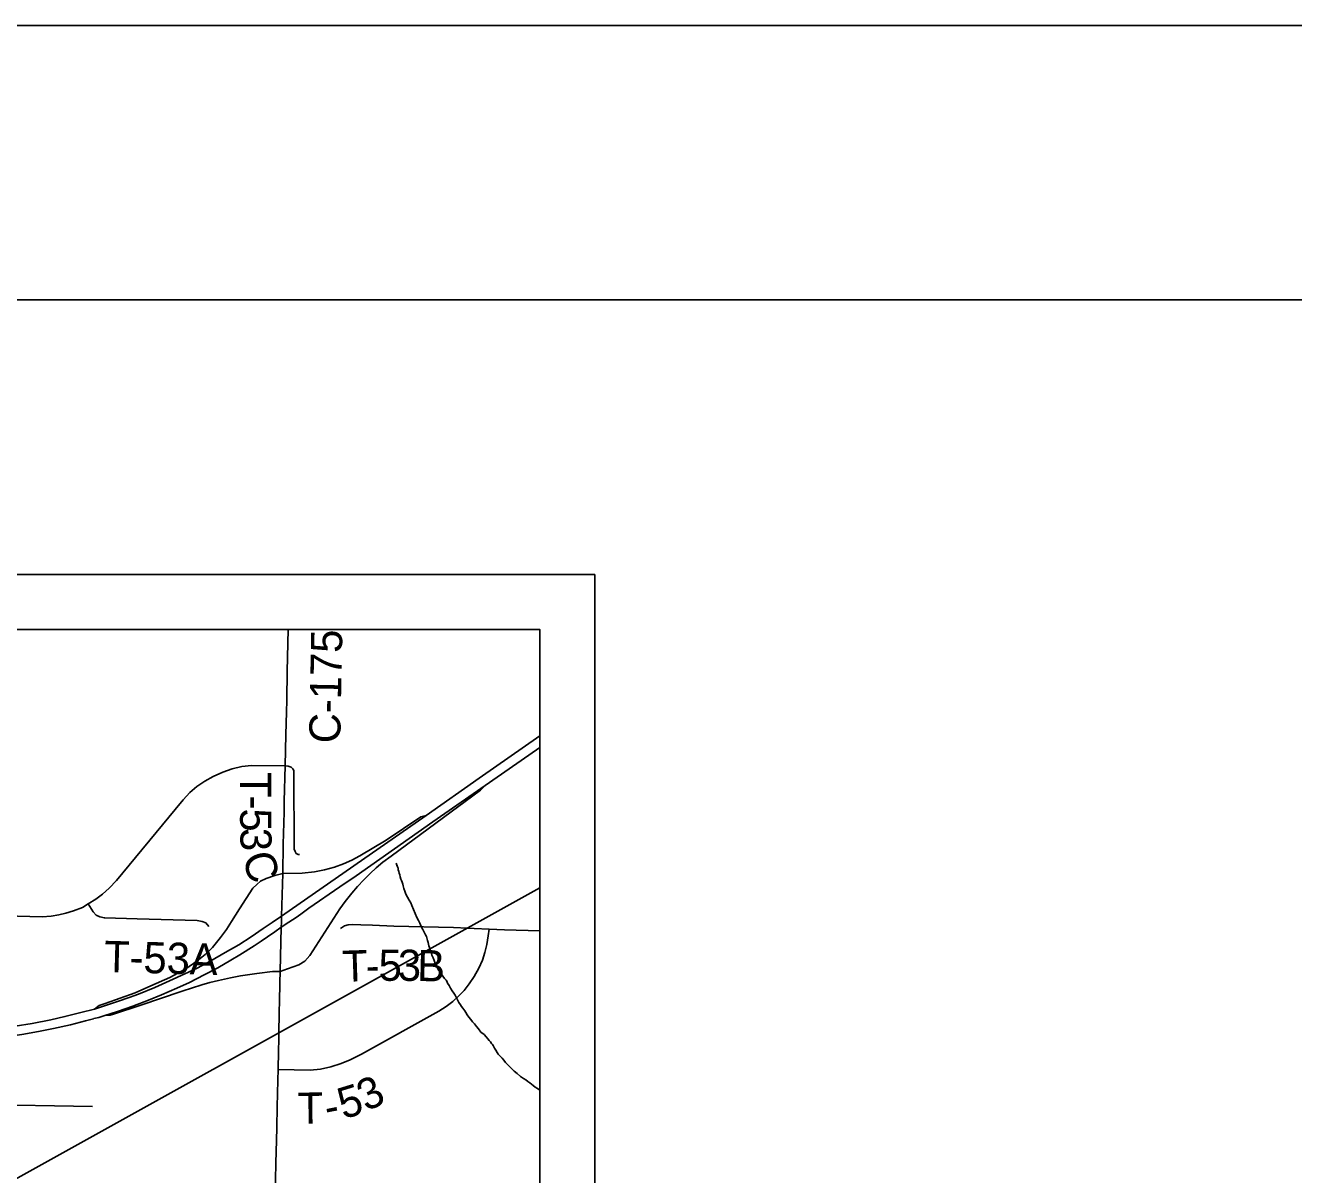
# Model space of a CAD drawing. Extents: x 0 to 34, y 0 to 22.
# Drawn here: x 29.379 to 31.69, y 19.908 to 22 of the extents above; entities that cross this region are included whole.
import ezdxf

# ---------------------------------------------------------------- set-up
doc = ezdxf.new("R2010")
doc.units = 0
for name, color, linetype in [('GM_X_City_Street', 7, 'Continuous'), ('GM_X_County_Road', 7, 'Continuous'), ('GM_X_County_Road_Text', 7, 'Continuous'), ('GM_X_Interchange_Ramps', 7, 'Continuous'), ('GM_X_Minor_River', 7, 'Continuous'), ('GM_X_Rail_Line', 7, 'Continuous'), ('GM_X_State_Route', 7, 'Continuous'), ('GM_X_Township_Road', 7, 'Continuous'), ('GM_X_Township_Road_Text', 7, 'Continuous'), ('GM_X_US_Route', 7, 'Continuous'), ('SH_Border', 7, 'Continuous'), ('SH_Cut_Line', 7, 'Continuous'), ('SH_Data', 7, 'Continuous')]:
    doc.layers.add(name, color=color, linetype=linetype)

msp = doc.modelspace()

# ---------------------------------------------------------------- linework, layer by layer
at = {"layer": 'GM_X_City_Street'}
msp.add_lwpolyline([(29.0843, 20.0386), (29.502, 20.0316)], dxfattribs=at)
at = {"layer": 'GM_X_County_Road'}
for points in [[(29.8555, 20.7716), (29.8566, 20.8244), (29.8584, 20.9)], [(29.8526, 20.6517), (29.8539, 20.7087), (29.855, 20.7498), (29.8555, 20.7716)], [(29.6523, 20.5721), (29.6669, 20.5897), (29.6793, 20.6033), (29.6918, 20.6142), (29.7062, 20.6241), (29.7214, 20.6326), (29.7394, 20.6405), (29.7562, 20.6461), (29.7736, 20.6504), (29.7911, 20.6523), (29.8526, 20.6517)], [(29.8506, 20.5677), (29.8511, 20.5875), (29.8526, 20.6517)], [(29.3428, 20.3785), (29.41, 20.3768), (29.4264, 20.3781), (29.4402, 20.3804), (29.4531, 20.3834), (29.4669, 20.3876), (29.4833, 20.3942), (29.4938, 20.4005), (29.5076, 20.409), (29.5198, 20.4179), (29.5323, 20.4291), (29.5454, 20.4432), (29.6523, 20.5721)], [(29.8483, 20.4557), (29.8492, 20.5092), (29.8506, 20.5677)]]:
    msp.add_lwpolyline(points, dxfattribs=at)
at = {"layer": 'GM_X_Interchange_Ramps'}
for points in [[(29.8433, 20.2774), (29.8568, 20.2821), (29.8775, 20.2893), (29.8887, 20.2959), (29.8979, 20.3068), (29.9522, 20.3913), (29.962, 20.4047), (29.9742, 20.4199), (29.9847, 20.4324), (29.9959, 20.4445), (30.0074, 20.456), (30.0186, 20.4662), (30.0308, 20.4764), (30.0456, 20.4876), (30.2088, 20.6077), (30.2172, 20.6163)], [(30.1096, 20.5615), (30.0999, 20.5587), (30.0369, 20.5162), (29.9887, 20.4879), (29.9742, 20.48), (29.9588, 20.4735), (29.9423, 20.4675), (29.9242, 20.4626), (29.9062, 20.459), (29.8835, 20.4564), (29.8483, 20.4557)]]:
    msp.add_lwpolyline(points, dxfattribs=at)
at = {"layer": 'GM_X_Minor_River'}
for points in [[(30.0547, 20.4746), (30.0572, 20.4681), (30.0561, 20.4708), (30.0572, 20.4681), (30.0583, 20.4658), (30.0586, 20.4627), (30.0596, 20.4596), (30.0603, 20.4566), (30.0613, 20.4531), (30.0623, 20.4497), (30.0634, 20.4455), (30.0648, 20.4428), (30.0659, 20.4401), (30.0669, 20.4366), (30.0679, 20.4332), (30.0689, 20.4286), (30.0707, 20.4236), (30.0728, 20.4182), (30.0757, 20.4128), (30.0786, 20.4074), (30.0815, 20.4024), (30.0836, 20.3978), (30.0864, 20.3904), (30.0893, 20.3828), (30.0925, 20.3758), (30.0957, 20.3704), (30.0982, 20.3654), (30.1007, 20.3596), (30.1036, 20.3538), (30.1061, 20.3488), (30.1083, 20.3442), (30.1101, 20.3411), (30.1108, 20.3384), (30.1118, 20.3338), (30.1132, 20.3304), (30.1138, 20.3273), (30.1145, 20.3243), (30.1156, 20.3208), (30.117, 20.317), (30.1184, 20.3127), (30.1201, 20.3074), (30.1222, 20.3024), (30.1244, 20.2974), (30.1261, 20.2928), (30.1279, 20.2893), (30.1294, 20.2866), (30.1304, 20.2843), (30.1311, 20.2823), (30.1329, 20.2789), (30.1362, 20.2742), (30.1399, 20.2688), (30.1432, 20.2645), (30.1457, 20.2618), (30.1472, 20.2598), (30.1486, 20.2564), (30.1512, 20.2521), (30.154, 20.2471), (30.1569, 20.2421), (30.1598, 20.2378), (30.1624, 20.2343), (30.1638, 20.2316), (30.1657, 20.2285), (30.1674, 20.2247), (30.1692, 20.2208), (30.1718, 20.2169), (30.174, 20.2138), (30.1762, 20.2107), (30.178, 20.2084), (30.1798, 20.2057), (30.182, 20.2026), (30.1845, 20.1983), (30.1874, 20.1941), (30.1907, 20.1902), (30.194, 20.1859), (30.1977, 20.182), (30.2014, 20.1773), (30.2051, 20.173), (30.2094, 20.1672), (30.2154, 20.1625), (30.2191, 20.1586), (30.222, 20.155), (30.2246, 20.1516), (30.2268, 20.1492), (30.2286, 20.1465), (30.2301, 20.1446), (30.2315, 20.1426), (30.2326, 20.1403), (30.234, 20.1376), (30.2362, 20.1341), (30.2391, 20.1302), (30.2409, 20.1271), (30.2431, 20.1244), (30.2453, 20.1221), (30.2479, 20.1193), (30.2509, 20.1158), (30.2542, 20.1119), (30.27, 20.0959), (30.2756, 20.0915), (30.2811, 20.0861), (30.2871, 20.0828), (30.2912, 20.0801)], [(30.2912, 20.0801), (30.2949, 20.0773), (30.2983, 20.0745), (30.3012, 20.0722), (30.3046, 20.0698), (30.3083, 20.067), (30.3124, 20.0642), (30.3167, 20.0615)]]:
    msp.add_lwpolyline(points, dxfattribs=at)
at = {"layer": 'GM_X_Rail_Line'}
msp.add_lwpolyline([(29.1835, 19.8007), (29.9023, 20.1997), (30.3167, 20.43)], dxfattribs=at)
at = {"layer": 'GM_X_State_Route'}
for p, q in [((29.755, 20.3685), (29.7696, 20.3912)), ((29.8433, 20.2774), (29.843, 20.2574))]:
    msp.add_line(p, q, dxfattribs=at)
for points in [[(29.7696, 20.3912), (29.794, 20.4291), (29.8009, 20.436), (29.8075, 20.4416), (29.8184, 20.4468), (29.8341, 20.4521), (29.8483, 20.4557), (29.846, 20.3781), (29.8458, 20.3665), (29.8456, 20.358), (29.8433, 20.2774)], [(29.5051, 20.2091), (29.5139, 20.2153), (29.5251, 20.219), (29.5793, 20.2387), (29.6079, 20.2512), (29.6428, 20.2666), (29.672, 20.2824), (29.6921, 20.2959), (29.7069, 20.3081), (29.7204, 20.3212), (29.7348, 20.3393), (29.7457, 20.3541), (29.755, 20.3685)], [(29.6672, 20.2424), (29.6819, 20.2473), (29.7008, 20.2532), (29.7156, 20.2576), (29.7315, 20.2611), (29.7532, 20.266), (29.7716, 20.2697), (29.8011, 20.2735), (29.8295, 20.2771), (29.8433, 20.2774)], [(29.5895, 20.2161), (29.6633, 20.2411), (29.6672, 20.2424)], [(29.843, 20.2574), (29.8428, 20.2464), (29.8423, 20.2323)], [(29.5243, 20.1974), (29.5338, 20.1981), (29.5403, 20.1995), (29.5895, 20.2161)], [(29.8423, 20.2323), (29.8422, 20.2282), (29.8417, 20.199), (29.8413, 20.1682), (29.8411, 20.1539)], [(29.8411, 20.1539), (29.8407, 20.1325), (29.84, 20.0988), (29.8396, 20.0796), (29.8384, 20.031), (29.8378, 19.9931), (29.8371, 19.9695), (29.8359, 19.929), (29.8346, 19.8657)]]:
    msp.add_lwpolyline(points, dxfattribs=at)
at = {"layer": 'GM_X_Township_Road'}
for points in [[(28.8021, 16.3696), (29.7483, 16.3505), (30.2361, 16.3375), (30.2681, 16.3359), (30.2735, 16.3357), (30.315, 16.335), (30.3167, 16.335), (30.3167, 20.9), (28.9104, 20.9)], [(29.8526, 20.6517), (29.8583, 20.651), (29.8635, 20.6496), (29.8666, 20.6465), (29.8687, 20.6434), (29.8687, 20.6399), (29.8694, 20.5001), (29.8708, 20.4956), (29.8725, 20.4921), (29.8764, 20.4904), (29.8791, 20.4904)], [(29.4938, 20.4005), (29.503, 20.386), (29.5086, 20.3801), (29.5152, 20.3768), (29.5234, 20.3748), (29.5244, 20.3748)], [(29.5244, 20.3748), (29.583, 20.3735), (29.6924, 20.3702)], [(29.6924, 20.3702), (29.7013, 20.3686), (29.7079, 20.3659), (29.7135, 20.3594)], [(29.84, 20.0988), (29.8982, 20.0976), (29.917, 20.0997), (29.936, 20.1035), (29.9548, 20.1097), (29.9714, 20.1167), (29.9919, 20.1271), (30.1324, 20.2052), (30.146, 20.2135), (30.1581, 20.2229), (30.1692, 20.2333), (30.1786, 20.2426), (30.1879, 20.2548), (30.197, 20.2683), (30.2056, 20.2832), (30.2122, 20.2978), (30.2167, 20.3117), (30.2202, 20.3266), (30.2226, 20.3426), (30.2244, 20.3544)], [(29.9538, 20.3558), (29.9607, 20.3604), (29.9673, 20.3623), (29.9752, 20.3627), (29.9905, 20.3622), (30.0116, 20.3615), (30.0508, 20.3602), (30.1595, 20.3572), (30.1857, 20.356)], [(30.1857, 20.356), (30.1968, 20.3555), (30.2244, 20.3544)], [(30.2244, 20.3544), (30.252, 20.3533), (30.3167, 20.3512)]]:
    msp.add_lwpolyline(points, dxfattribs=at)
at = {"layer": 'GM_X_US_Route'}
for p, q in [((30.2064, 20.6293), (30.3167, 20.7065)), ((30.1096, 20.5615), (30.2064, 20.6293))]:
    msp.add_line(p, q, dxfattribs=at)
for points in [[(30.2172, 20.6163), (30.2964, 20.6713), (30.3167, 20.6855)], [(29.8456, 20.358), (29.8596, 20.3675), (29.8727, 20.3759), (29.8812, 20.382), (29.8957, 20.3926), (29.9521, 20.4313), (29.9818, 20.4518), (30.1217, 20.5501), (30.2172, 20.6163)], [(29.8292, 20.3668), (29.846, 20.3781), (30.1096, 20.5615)], [(29.361, 20.1779), (29.3916, 20.1825), (29.4258, 20.1894), (29.4514, 20.1953), (29.4803, 20.2025), (29.5051, 20.2091), (29.5293, 20.2167), (29.5491, 20.2232), (29.5688, 20.2301), (29.5856, 20.2364), (29.6152, 20.2482), (29.6421, 20.2601), (29.6701, 20.2729), (29.6924, 20.2837), (29.7174, 20.2969), (29.7437, 20.312), (29.7681, 20.3262), (29.7907, 20.3406), (29.8124, 20.3554), (29.8292, 20.3668)], [(29.5243, 20.1974), (29.5474, 20.2047), (29.575, 20.2143), (29.6035, 20.2251), (29.6277, 20.2349), (29.6551, 20.2468), (29.6782, 20.2576), (29.7054, 20.2712), (29.7301, 20.2843), (29.7539, 20.2978), (29.7699, 20.3075), (29.7961, 20.3242), (29.8087, 20.3327), (29.8204, 20.3405), (29.8337, 20.3497), (29.8456, 20.358)], [(29.5044, 20.1915), (29.5131, 20.1939), (29.5243, 20.1974)], [(29.0865, 20.149), (29.0875, 20.149), (29.1993, 20.1493), (29.2371, 20.1501), (29.2676, 20.1514), (29.2948, 20.1532), (29.3208, 20.1557), (29.3473, 20.1589), (29.3731, 20.1627), (29.4031, 20.1679), (29.4305, 20.1734), (29.4614, 20.1804), (29.4891, 20.1874), (29.5035, 20.1912), (29.5044, 20.1915)]]:
    msp.add_lwpolyline(points, dxfattribs=at)
at = {"layer": 'SH_Border'}
msp.add_lwpolyline([(1.5, 21.5), (33.5, 21.5), (33.5, 0.5), (1.5, 0.5)], close=True, dxfattribs=at)
at = {"layer": 'SH_Cut_Line'}
msp.add_lwpolyline([(0, 0), (34, 0), (34, 22), (0, 22)], close=True, dxfattribs=at)
at = {"layer": 'SH_Data'}
for points in [[(23.4167, 21), (30.4167, 21), (30.4167, 14), (23.4167, 14)], [(23.5167, 20.9), (30.3167, 20.9), (30.3167, 14.1), (23.5167, 14.1)]]:
    msp.add_lwpolyline(points, close=True, dxfattribs=at)

# ---------------------------------------------------------------- texts
at = {"layer": 'GM_X_County_Road_Text'}
msp.add_text('C-175', height=0.05682, rotation=88.8984, dxfattribs=at).set_placement((29.953, 20.6925))
at = {"layer": 'GM_X_Township_Road_Text'}
for s, height, rotation, p in [('T', 0.0568, 270.0064, (29.7706, 20.6402)), ('-', 0.0568, 270.0505, (29.7706, 20.5977)), ('5', 0.0568, 270.2365, (29.7706, 20.5742)), ('3', 0.0568, 271.0412, (29.7708, 20.5383)), ('C', 0.0568, 286.8415, (29.774, 20.4865)), ('T-53A', 0.05682, 358.4517, (29.5223, 20.2766)), ('T', 0.0568, 1.9074, (29.9577, 20.2584)), ('5', 0.0568, 0.3122, (30.0231, 20.2603)), ('3', 0.0568, 359.4744, (30.0578, 20.2605)), ('B', 0.0568, 358.5519, (30.0926, 20.2602)), ('-', 0.0568, 1.3505, (30, 20.2598)), ('3', 0.0568, 25.9824, (30.001, 20.0217)), ('T', 0.0568, 0.7243, (29.8759, 20)), ('5', 0.0568, 17.1989, (29.9588, 20.0079)), ('-', 0.0568, 11.1567, (29.9296, 20.0017))]:
    msp.add_text(s, height=height, rotation=rotation, dxfattribs=at).set_placement(p)

doc.saveas('drawing.dxf')
